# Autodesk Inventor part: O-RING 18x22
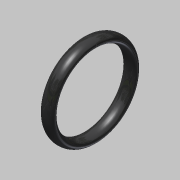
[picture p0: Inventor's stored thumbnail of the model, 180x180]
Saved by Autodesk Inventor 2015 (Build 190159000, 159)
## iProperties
Created: 2020-02
Part Number: O-RING 18x22
Material: 고무
Document SubType Name: Modeling
Designer: mduedu
Density: 1 g/cm^3
Appearance: 고무 - 검은색 - 버전 1.1
Author: mduedu
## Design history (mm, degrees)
sketch "스케치1"
  geometry: L1 (-2.24, 0)-(2.24, 0) reference; L2 (-1.6, 10)-(1.6, 10); L3 (0, 11)-(0, 9); 6 further points; 1 other entity
  constraints: 4 coincident, 4 end point, 2 horizontal, 2 midpoint, 1 vertical, 1 vertical alignment, 6 other
  dimensions: "d0" = 18 diameter of point (0, 9) L1; "d1" = 22 diameter of point (0, 11) L1; "d2" = 1.6 distance from line of point (1.6, 10) L3
revolve "회전1" sketch "스케치1" stored, may be unused: angle "d3" = 90 deg
node "솔리드1"
